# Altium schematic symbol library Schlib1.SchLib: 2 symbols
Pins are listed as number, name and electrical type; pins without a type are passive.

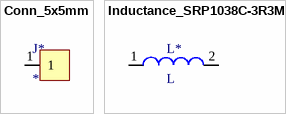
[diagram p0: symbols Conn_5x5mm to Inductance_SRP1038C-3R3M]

## Conn_5x5mm
designator J*
footprint Conn_5x5mm
pins: 1

## Inductance_SRP1038C-3R3M
designator L*, comment L
SRP1038C-3R3M 3.3 uH; 11.8 mOhms; 14 A
footprint Inductance_SRP1038C-3R3M
pins: 1, 2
